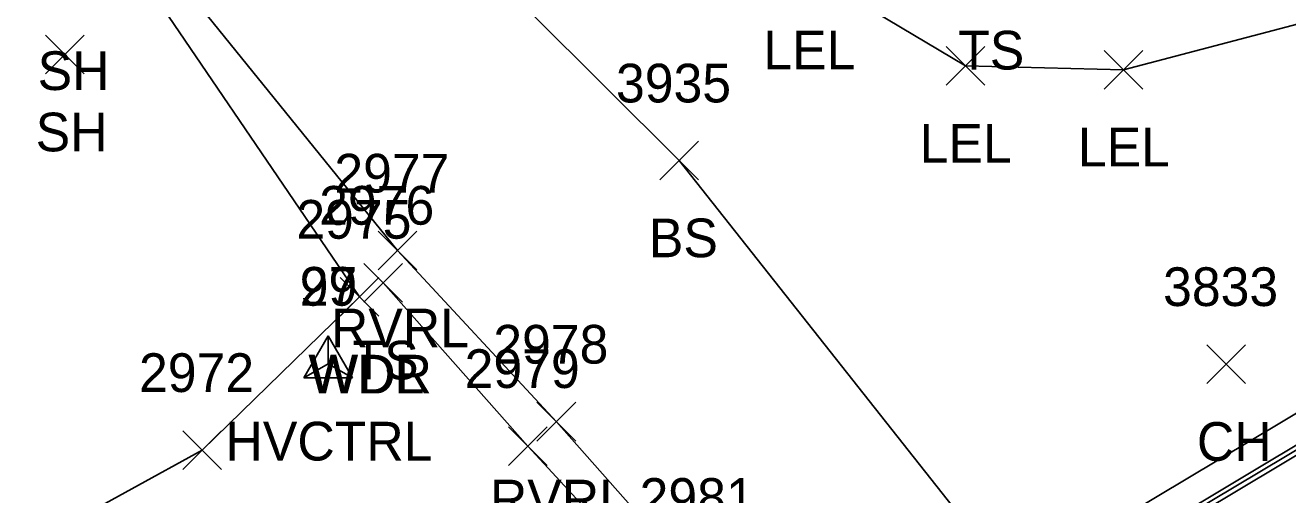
# Model space of a CAD drawing. Extents: x 1443590 to 1445966, y 578314 to 580556.
# Drawn here: x 1444183.6 to 1444248.9, y 578972.2 to 578996.5 of the extents above; entities that cross this region are included whole.
import ezdxf

# ---------------------------------------------------------------- set-up
doc = ezdxf.new("R2010")
doc.units = 0
for name, color, linetype in [('BB', 7, 'Continuous'), ('BDC', 7, 'Continuous'), ('BELB', 7, 'Continuous'), ('BF', 7, 'Continuous'), ('C_A', 7, 'Continuous'), ('C_I', 7, 'Continuous'), ('CPSM', 7, 'Continuous'), ('L_A', 7, 'Continuous'), ('L_I', 7, 'Continuous'), ('L_TIC', 7, 'Continuous'), ('LARO', 7, 'Continuous'), ('LAWA', 7, 'Continuous'), ('LAWE', 7, 'Continuous'), ('LELB', 7, 'Continuous')]:
    doc.layers.add(name, color=color, linetype=linetype)

msp = doc.modelspace()

# ---------------------------------------------------------------- linework, layer by layer
at = {"layer": 'BB'}
msp.add_lwpolyline([(1444205.61, 578948.082), (1444265.76, 578984.059)], dxfattribs=at)
at = {"layer": 'BDC'}
msp.add_lwpolyline([(1444393.513, 579062.489), (1444394.118, 579061.308), (1444330.705, 579023.404), (1444267.078, 578985.387), (1444205.127, 578948.274), (1444203.399, 578948.665), (1444203.223, 578948.843)], dxfattribs=at)
at = {"layer": 'BELB'}
msp.add_lwpolyline([(1444394.46, 579061.264), (1444330.853, 579023.124), (1444267.263, 578985.215), (1444204.094, 578947.486)], dxfattribs=at)
at = {"layer": 'BF'}
msp.add_lwpolyline([(1444393.513, 579062.489), (1444330.042, 579024.651), (1444266.432, 578986.627), (1444203.223, 578948.843)], dxfattribs=at)
at = {"layer": 'CPSM'}
for p, q in [((1444198.03, 578978.243), (1444199.28, 578980.408)), ((1444198.031, 578978.244), (1444199.281, 578980.409)), ((1444200.53, 578978.243), (1444199.28, 578980.408)), ((1444199.281, 578978.964), (1444199.28, 578980.408)), ((1444200.531, 578978.244), (1444199.281, 578980.409)), ((1444199.281, 578978.965), (1444199.281, 578980.409)), ((1444198.03, 578978.243), (1444199.281, 578978.964)), ((1444198.031, 578978.244), (1444199.281, 578978.965)), ((1444199.281, 578978.965), (1444199.281, 578978.965)), ((1444199.281, 578978.965), (1444200.531, 578978.244)), ((1444199.281, 578978.964), (1444199.281, 578978.964)), ((1444199.281, 578978.964), (1444200.53, 578978.243)), ((1444198.03, 578978.243), (1444200.53, 578978.243)), ((1444198.031, 578978.244), (1444200.531, 578978.244))]:
    msp.add_line(p, q, dxfattribs=at)
at = {"layer": 'L_TIC'}
for points in [[(1444184.673, 578993.94), (1444186.673, 578995.94)], [(1444186.673, 578993.94), (1444184.673, 578995.94)], [(1444231.223, 578993.359), (1444233.223, 578995.359)], [(1444233.223, 578993.359), (1444231.223, 578995.359)], [(1444239.396, 578993.158), (1444241.396, 578995.158)], [(1444241.396, 578993.158), (1444239.396, 578995.158)], [(1444216.42, 578988.468), (1444218.42, 578990.468)], [(1444218.42, 578988.468), (1444216.42, 578990.468)], [(1444216.42, 578988.468), (1444218.42, 578990.468)], [(1444218.42, 578988.468), (1444216.42, 578990.468)], [(1444201.859, 578983.811), (1444203.859, 578985.811)], [(1444203.859, 578983.811), (1444201.859, 578985.811)], [(1444201.131, 578982.151), (1444203.131, 578984.151)], [(1444203.131, 578982.151), (1444201.131, 578984.151)], [(1444199.896, 578981.427), (1444201.896, 578983.427)], [(1444201.896, 578981.427), (1444199.896, 578983.427)], [(1444199.896, 578981.427), (1444201.896, 578983.427)], [(1444201.896, 578981.427), (1444199.896, 578983.427)], [(1444244.702, 578977.947), (1444246.702, 578979.947)], [(1444246.702, 578977.947), (1444244.702, 578979.947)], [(1444210.076, 578974.971), (1444212.076, 578976.971)], [(1444212.076, 578974.971), (1444210.076, 578976.971)], [(1444208.603, 578973.712), (1444210.603, 578975.712)], [(1444210.603, 578973.712), (1444208.603, 578975.712)], [(1444191.762, 578973.505), (1444193.762, 578975.505)], [(1444193.762, 578973.505), (1444191.762, 578975.505)]]:
    msp.add_lwpolyline(points, dxfattribs=at)
at = {"layer": 'LARO'}
msp.add_lwpolyline([(1444279.856, 579026.505), (1444267.879, 579037.19), (1444253.982, 579041.227), (1444241.883, 579037.126), (1444227.234, 579040.504), (1444212.692, 579023.706), (1444212.697, 579015.908), (1444215.127, 579005.479), (1444224.14, 578999.182), (1444232.223, 578994.359), (1444240.396, 578994.158), (1444256.525, 578998.412), (1444269.048, 579003.331)], dxfattribs=at)
at = {"layer": 'LAWA'}
for points in [[(1444164.589, 579023.191), (1444151.39, 579010.208), (1444135.888, 578991.769), (1444129.866, 578980.22), (1444131.127, 578969), (1444144.826, 578962.172), (1444142.06, 578943.775), (1444162.189, 578960.759), (1444178.207, 578966.501), (1444192.762, 578974.505), (1444200.896, 578982.427)], [(1444164.589, 579023.191), (1444173.049, 579017.23), (1444187.645, 579001.911), (1444200.896, 578982.427)]]:
    msp.add_lwpolyline(points, dxfattribs=at)
at = {"layer": 'LAWE'}
msp.add_lwpolyline([(1444132.863, 579092.153), (1444138.962, 579083.211), (1444141.194, 579057.076), (1444148.069, 579045.276), (1444167.245, 579025.017), (1444174.77, 579019.565), (1444188.422, 579002.667), (1444202.859, 578984.811), (1444211.076, 578975.971), (1444218.072, 578968.054), (1444223.321, 578965.926), (1444225.772, 578959.776), (1444234.825, 578940.518), (1444239.555, 578925.633), (1444236.716, 578915.571)], dxfattribs=at)
at = {"layer": 'LELB'}
for points in [[(1444147.298, 579085.746), (1444154.301, 579067.935), (1444160.7, 579051.507), (1444170.685, 579032.777), (1444198.185, 579008.645), (1444217.42, 578989.468)], [(1444242.727, 578946.45), (1444235.646, 578966.441), (1444217.42, 578989.468)], [(1444202.131, 578983.151), (1444209.603, 578974.712), (1444216.697, 578967.02), (1444221.206, 578964.775), (1444223.649, 578959.432), (1444233.298, 578939.564), (1444234.323, 578936.96)]]:
    msp.add_lwpolyline(points, dxfattribs=at)

# ---------------------------------------------------------------- texts
at = {"layer": 'C_A'}
for p in [(1444193.974, 578973.965), (1444193.974, 578973.964)]:
    msp.add_text('HVCTRL', height=2, dxfattribs=at).set_placement(p)
at = {"layer": 'C_I'}
for s, p in [('99', (1444197.809, 578981.965)), ('27', (1444197.816, 578981.964))]:
    msp.add_text(s, height=2, dxfattribs=at).set_placement(p)
at = {"layer": 'L_A'}
for s, p in [('LEL', (1444221.777, 578994.182)), ('TS', (1444231.85, 578994.17)), ('SH', (1444184.261, 578993.11)), ('SH', (1444184.161, 578989.94)), ('LEL', (1444229.861, 578989.359)), ('LEL', (1444238.034, 578989.158)), ('BS', (1444215.861, 578984.468)), ('BS', (1444215.861, 578984.468)), ('RVRL', (1444199.426, 578979.811)), ('TS', (1444200.541, 578978.151)), ('WDR', (1444198.258, 578977.427)), ('WDL', (1444198.313, 578977.427)), ('CH', (1444244.19, 578973.947)), ('RVRL', (1444207.643, 578970.971))]:
    msp.add_text(s, height=2, dxfattribs=at).set_placement(p)
at = {"layer": 'L_I'}
for s, p in [('3935', (1444214.16, 578992.468)), ('3935', (1444214.16, 578992.468)), ('2977', (1444199.599, 578987.811)), ('2976', (1444198.816, 578986.151)), ('2975', (1444197.636, 578985.427)), ('2975', (1444197.636, 578985.427)), ('3833', (1444242.442, 578981.947)), ('2978', (1444207.816, 578978.971)), ('2979', (1444206.335, 578977.712)), ('2972', (1444189.502, 578977.505)), ('2981', (1444215.38, 578971.054))]:
    msp.add_text(s, height=2, dxfattribs=at).set_placement(p)

doc.saveas('drawing.dxf')
